Omron CX-Programmer project Vízmű_demo (CX-Programmer 3.01)

# PLC Vízmű_SMS: CQM1H CPU51

## Program Vízmű (no task)
Local symbols
Adat_vétel AR8.06 BOOL
Bekapcs_tár HR6 CHANNEL  ; A bekapcsolt kimenetek tárolására
Főkapcs_be DM0 CHANNEL  ; Főkapcsoló bekapcsolt string
Főkapcs_ki DM40 CHANNEL  ; Főkapcsoló kikapcsolt string
Főkapcsoló 0.00 BOOL  ; Főkapcsoló
Főkapcsoló_l 100.00 BOOL  ; Főkapcsoló visszajelzés
Hiba_l 100.15 BOOL  ; Hiba visszajelzés
Kikapcs_tár HR7 CHANNEL  ; A kikapcsolt kimenetek tárolására
Kim_vált 50.00 BOOL  ; Változás a kimenetei bitek között
Komm_step 50.05 BOOL  ; Jelzi, ha a kommunikációs lépéssorozat aktív
M1 100.10 BOOL  ; Egyes motor visszajelzés
M1_H 0.05 BOOL  ; Egyes motor hőkioldó
M1_H_be DM240 CHANNEL  ; Egyes motor hőkioldó bekapcsolt string
M1_H_ki DM280 CHANNEL  ; Egyes motor hőkioldő kikapcsolt string
M1_H_l 100.05 BOOL  ; Egyes motor hőkioldó visszajelzés
M1_be DM80 CHANNEL  ; Egyes motor bekapcsolt string
M1_ki DM120 CHANNEL  ; Egyes motor kikapcsolt string
M2 100.11 BOOL  ; Kettes motor visszajelzés
M2_H 0.06 BOOL  ; Kettes motor hőkioldó
M2_H_be DM320 CHANNEL  ; Kettes moror hőkioldó bekapcsolt string
M2_H_ki DM360 CHANNEL  ; Kettes motor hőkioldó kikapcsolt string
M2_H_l 100.06 BOOL  ; Kettes motor hőkioldó visszajelzés
M2_be DM160 CHANNEL  ; Kettes motor bekapcsolt sting
M2_ki DM200 CHANNEL  ; Kettes motor kikapcsolt string
OK_Text DM1000 CHANNEL  ; Az OK sting-et tartalmazó memóriaterület címe.
Port_send_OK AR8.05 BOOL
Port_setup_OK AR24.04 BOOL  ; Az RS232C port átállítása megtörtént
SMS_Port_Ok BOOL
SMS_Prompt_Text DM1001 CHANNEL  ; A > promptot tartalmazó memóraterület címe
SMS_Start_Text DM1020 CHANNEL  ; At SMS küldést jelző string kezdőcíme. Tartalmazza a telefonszámot is DM1026-tól kezdődően.
Text_Mode_Text DM1010 CHANNEL  ; A text módot kiválasztó string kezdőcíme.
dm CHANNEL

### Section Vezérlés

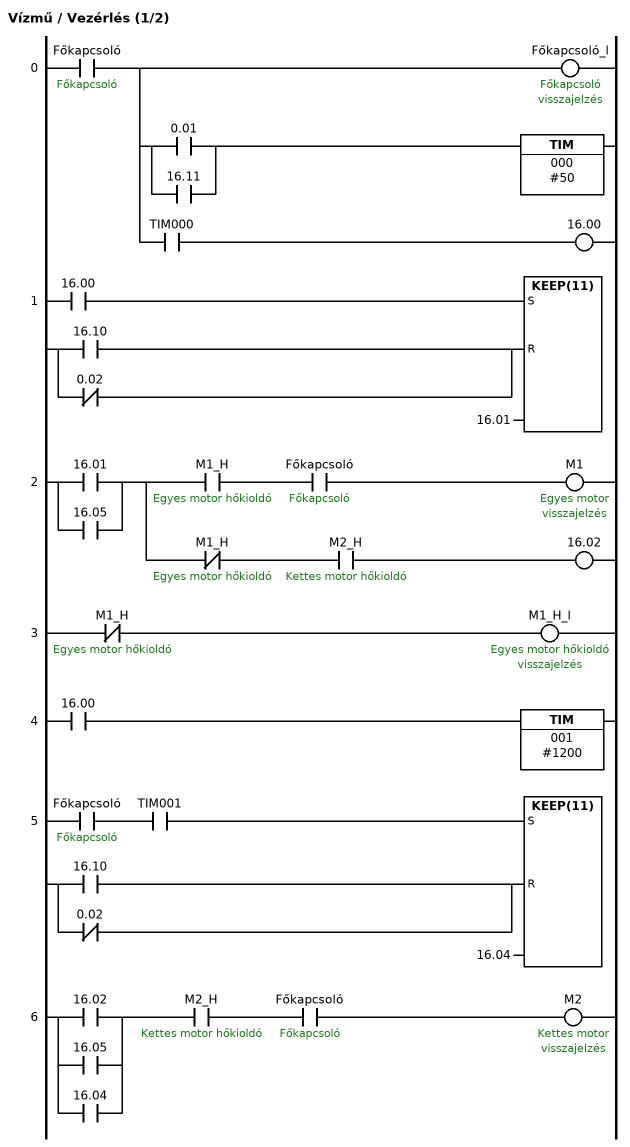
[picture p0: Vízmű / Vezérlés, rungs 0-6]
; rung 0
LD Főkapcsoló  ; Főkapcsoló
OUT TR0
OUT Főkapcsoló_l  ; Főkapcsoló visszajelzés
LD 0.01
OR 16.11
ANDLD
TIM 000 #50
LD TR0
AND TIM000
OUT 16.00
; rung 1
LD 16.00
LD 16.10
ORNOT 0.02
KEEP(11) 16.01
; rung 2
LD 16.01
OR 16.05
OUT TR0
AND M1_H  ; Egyes motor hőkioldó
AND Főkapcsoló  ; Főkapcsoló
OUT M1  ; Egyes motor visszajelzés
LD TR0
ANDNOT M1_H  ; Egyes motor hőkioldó
AND M2_H  ; Kettes motor hőkioldó
OUT 16.02
; rung 3
LDNOT M1_H  ; Egyes motor hőkioldó
OUT M1_H_l  ; Egyes motor hőkioldó visszajelzés
; rung 4
LD 16.00
TIM 001 #1200
; rung 5
LD Főkapcsoló  ; Főkapcsoló
AND TIM001
LD 16.10
ORNOT 0.02
KEEP(11) 16.04
; rung 6
LD 16.02
OR 16.05
OR 16.04
AND M2_H  ; Kettes motor hőkioldó
AND Főkapcsoló  ; Főkapcsoló
OUT M2  ; Kettes motor visszajelzés

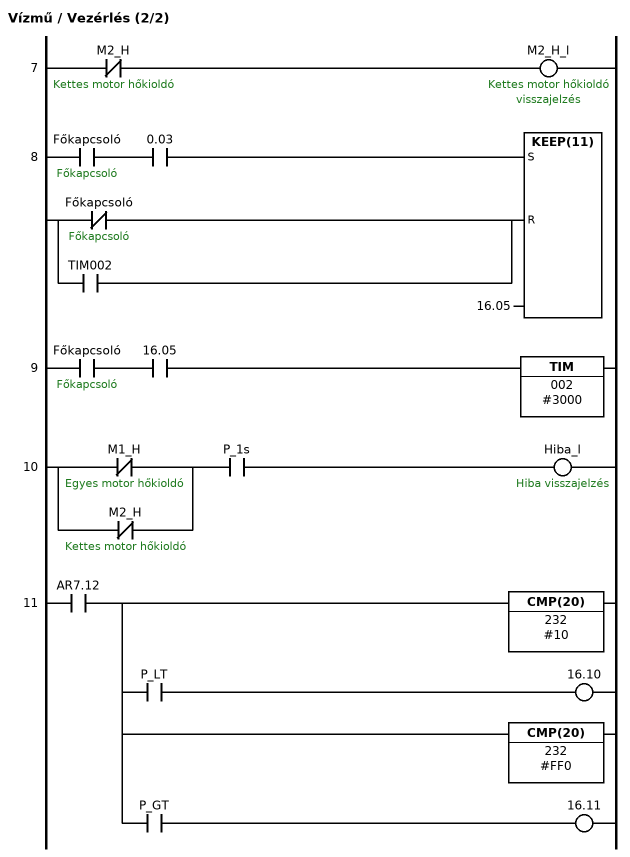
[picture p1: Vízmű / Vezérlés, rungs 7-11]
; rung 7
LDNOT M2_H  ; Kettes motor hőkioldó
OUT M2_H_l  ; Kettes motor hőkioldó visszajelzés
; rung 8
LD Főkapcsoló  ; Főkapcsoló
AND 0.03
LDNOT Főkapcsoló  ; Főkapcsoló
OR TIM002
KEEP(11) 16.05
; rung 9
LD Főkapcsoló  ; Főkapcsoló
AND 16.05
TIM 002 #3000
; rung 10
LDNOT M1_H  ; Egyes motor hőkioldó
ORNOT M2_H  ; Kettes motor hőkioldó
AND P_1s
OUT Hiba_l  ; Hiba visszajelzés
; rung 11
LD AR7.12
OUT TR0
CMP(20) 232 #10
AND P_LT
OUT 16.10
LD TR0
CMP(20) 232 #FF0
AND P_GT
OUT 16.11

### Section Kommunikáció

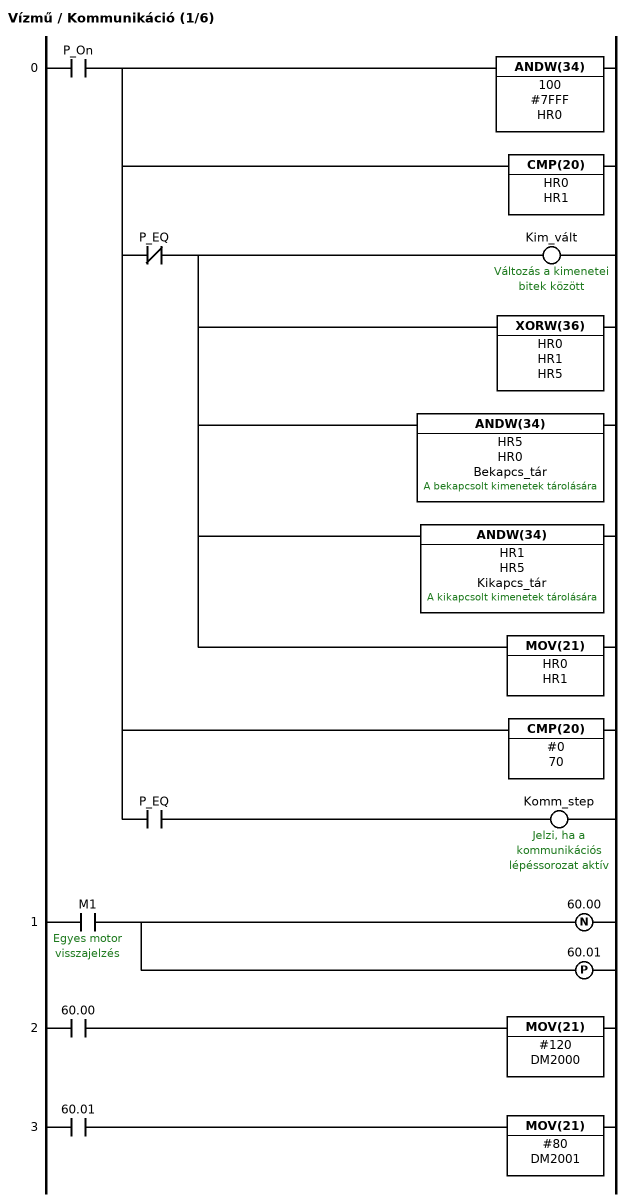
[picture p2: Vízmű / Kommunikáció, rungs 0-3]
; rung 0
LD P_On
OUT TR0
ANDW(34) 100 #7FFF HR0
CMP(20) HR0 HR1
ANDNOT P_EQ
OUT Kim_vált  ; Változás a kimenetei bitek között
XORW(36) HR0 HR1 HR5
ANDW(34) HR5 HR0 Bekapcs_tár  ; A bekapcsolt kimenetek tárolására
ANDW(34) HR1 HR5 Kikapcs_tár  ; A kikapcsolt kimenetek tárolására
MOV(21) HR0 HR1
LD TR0
CMP(20) #0 70
AND P_EQ
OUT Komm_step  ; Jelzi, ha a kommunikációs lépéssorozat aktív
; rung 1
LD M1  ; Egyes motor visszajelzés
DIFD(14) 60.00
DIFU(13) 60.01
; rung 2
LD 60.00
MOV(21) #120 DM2000
; rung 3
LD 60.01
MOV(21) #80 DM2001

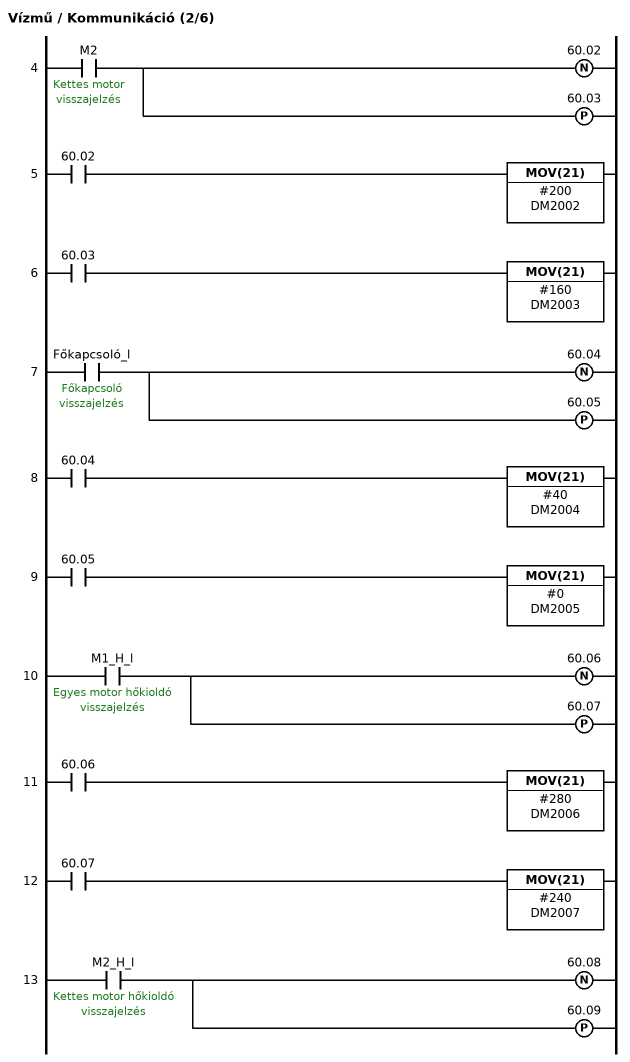
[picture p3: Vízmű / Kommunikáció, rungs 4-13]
; rung 4
LD M2  ; Kettes motor visszajelzés
DIFD(14) 60.02
DIFU(13) 60.03
; rung 5
LD 60.02
MOV(21) #200 DM2002
; rung 6
LD 60.03
MOV(21) #160 DM2003
; rung 7
LD Főkapcsoló_l  ; Főkapcsoló visszajelzés
DIFD(14) 60.04
DIFU(13) 60.05
; rung 8
LD 60.04
MOV(21) #40 DM2004
; rung 9
LD 60.05
MOV(21) #0 DM2005
; rung 10
LD M1_H_l  ; Egyes motor hőkioldó visszajelzés
DIFD(14) 60.06
DIFU(13) 60.07
; rung 11
LD 60.06
MOV(21) #280 DM2006
; rung 12
LD 60.07
MOV(21) #240 DM2007
; rung 13
LD M2_H_l  ; Kettes motor hőkioldó visszajelzés
DIFD(14) 60.08
DIFU(13) 60.09

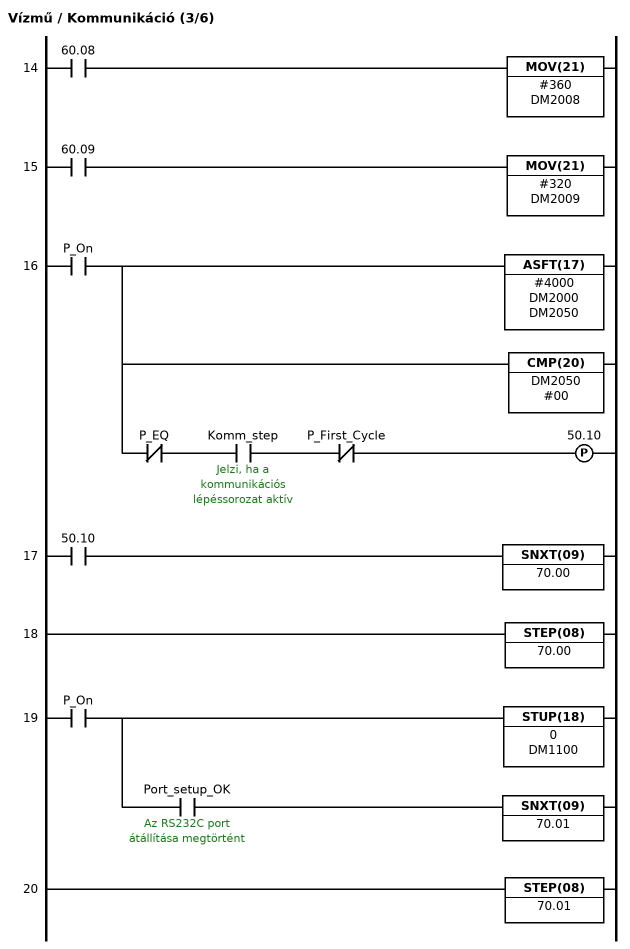
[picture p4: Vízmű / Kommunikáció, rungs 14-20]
; rung 14
LD 60.08
MOV(21) #360 DM2008
; rung 15
LD 60.09
MOV(21) #320 DM2009
; rung 16
LD P_On
ASFT(17) #4000 DM2000 DM2050
CMP(20) DM2050 #00
ANDNOT P_EQ
AND Komm_step  ; Jelzi, ha a kommunikációs lépéssorozat aktív
ANDNOT P_First_Cycle
DIFU(13) 50.10
; rung 17
LD 50.10
SNXT(09) 70.00
; rung 18
STEP(08) 70.00
; rung 19
LD P_On
STUP(18) 0 DM1100
AND Port_setup_OK  ; Az RS232C port átállítása megtörtént
SNXT(09) 70.01
; rung 20
STEP(08) 70.01

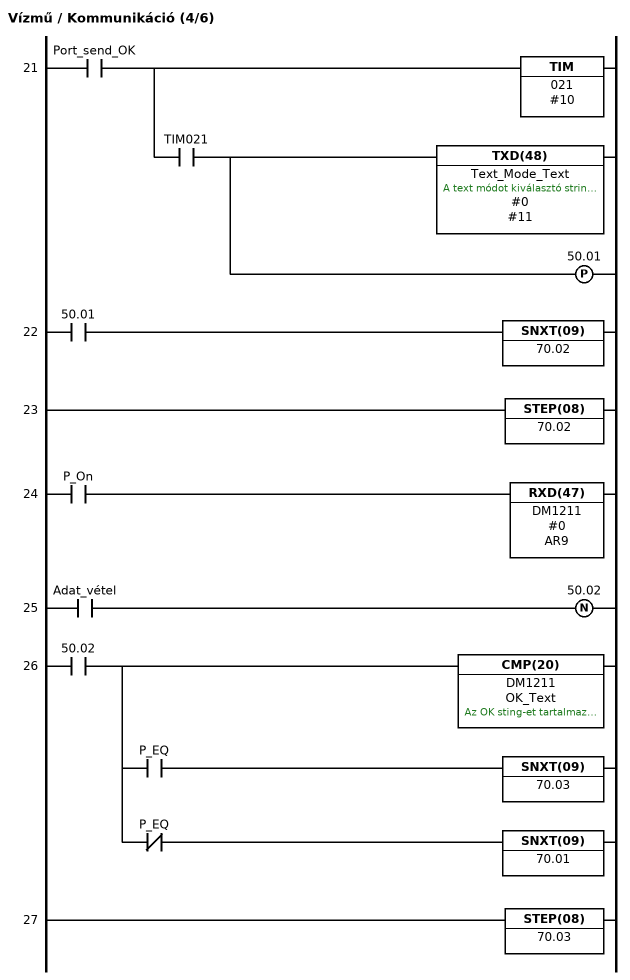
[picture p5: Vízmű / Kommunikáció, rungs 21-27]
; rung 21
LD Port_send_OK
TIM 021 #10
AND TIM021
TXD(48) Text_Mode_Text #0 #11  ; A text módot kiválasztó string kezdőcíme.
DIFU(13) 50.01
; rung 22
LD 50.01
SNXT(09) 70.02
; rung 23
STEP(08) 70.02
; rung 24
LD P_On
RXD(47) DM1211 #0 AR9
; rung 25
LD Adat_vétel
DIFD(14) 50.02
; rung 26
LD 50.02
OUT TR0
CMP(20) DM1211 OK_Text  ; Az OK sting-et tartalmazó memóriaterület címe.
AND P_EQ
SNXT(09) 70.03
LD TR0
ANDNOT P_EQ
SNXT(09) 70.01
; rung 27
STEP(08) 70.03

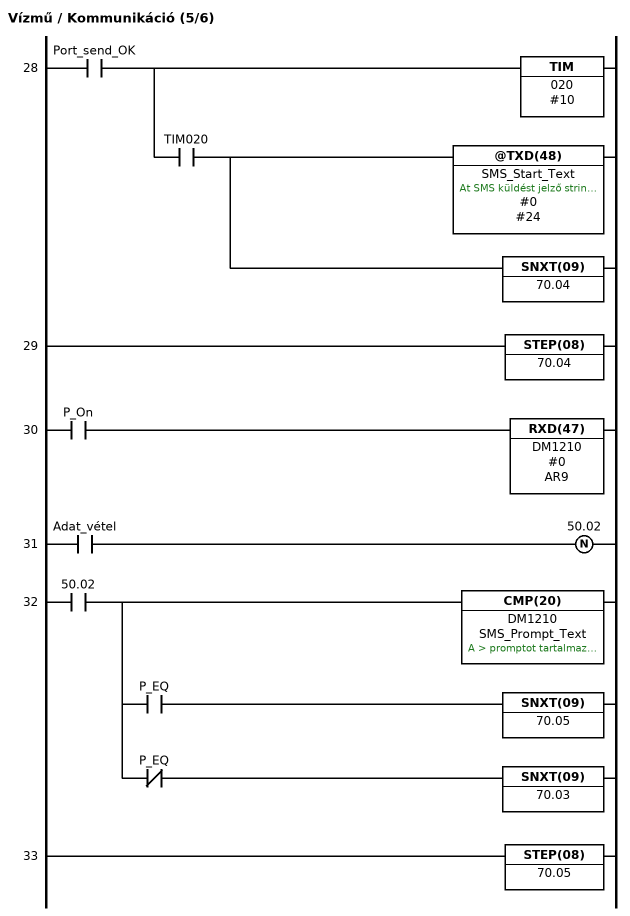
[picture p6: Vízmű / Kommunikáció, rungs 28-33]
; rung 28
LD Port_send_OK
TIM 020 #10
AND TIM020
@TXD(48) SMS_Start_Text #0 #24  ; At SMS küldést jelző string kezdőcíme. Tartalmazza a telefonszámot is DM1026-tól kezdődően.
SNXT(09) 70.04
; rung 29
STEP(08) 70.04
; rung 30
LD P_On
RXD(47) DM1210 #0 AR9
; rung 31
LD Adat_vétel
DIFD(14) 50.02
; rung 32
LD 50.02
OUT TR0
CMP(20) DM1210 SMS_Prompt_Text  ; A > promptot tartalmazó memóraterület címe
AND P_EQ
SNXT(09) 70.05
LD TR0
ANDNOT P_EQ
SNXT(09) 70.03
; rung 33
STEP(08) 70.05

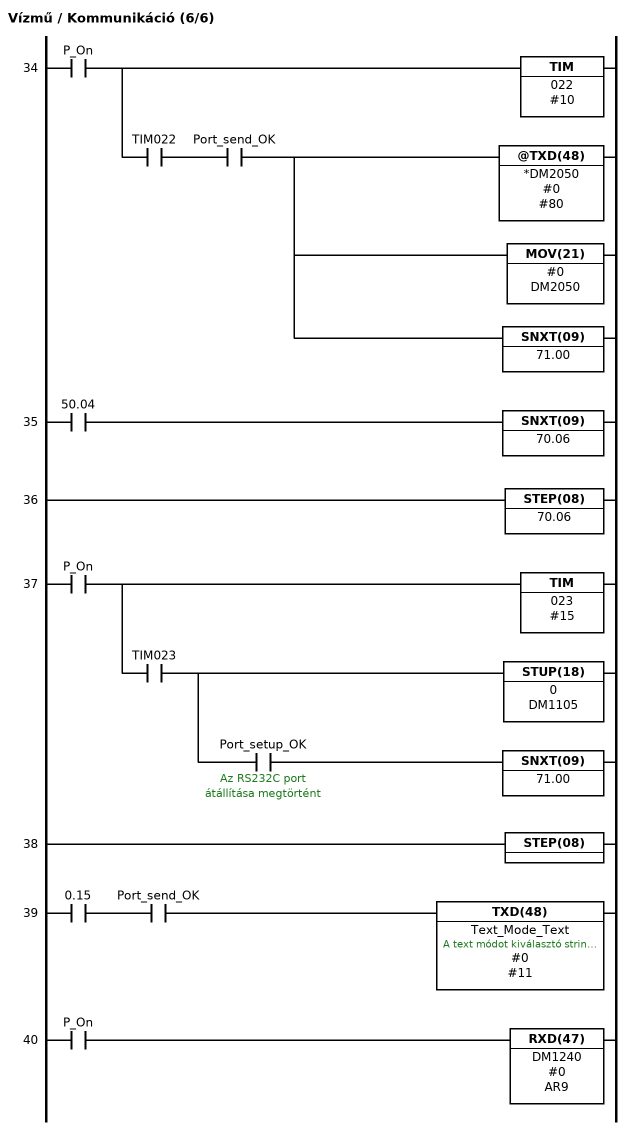
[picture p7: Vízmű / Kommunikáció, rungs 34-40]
; rung 34
LD P_On
TIM 022 #10
AND TIM022
AND Port_send_OK
@TXD(48) *DM2050 #0 #80
MOV(21) #0 DM2050
SNXT(09) 71.00
; rung 35
LD 50.04
SNXT(09) 70.06
; rung 36
STEP(08) 70.06
; rung 37
LD P_On
TIM 023 #15
AND TIM023
STUP(18) 0 DM1105
AND Port_setup_OK  ; Az RS232C port átállítása megtörtént
SNXT(09) 71.00
; rung 38
STEP(08)
; rung 39
LD 0.15
AND Port_send_OK
TXD(48) Text_Mode_Text #0 #11  ; A text módot kiválasztó string kezdőcíme.
; rung 40
LD P_On
RXD(47) DM1240 #0 AR9

### Section END
; rung 0
END(01)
